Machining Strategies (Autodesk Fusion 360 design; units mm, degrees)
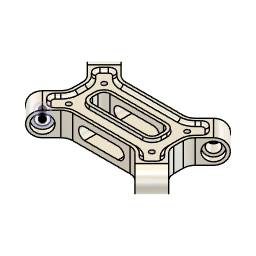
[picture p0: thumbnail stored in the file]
base_feature "Base Feature1" bodies "Screw", "Pull Stud", "Base", "Pull Stud (1)", "Pull Stud (2)", "Pull Stud (3)"
base_feature "Base Feature1"
base_feature "Base Feature1"
as_built_joint "As-built1"
as_built_joint "As-built4"
as_built_joint "As-built2" OffsetX 0 OffsetY 0 OffsetZ 0 AngleZ 0 DistanceMinimum 0
as_built_joint "As-built3" OffsetX 0 OffsetY 0 OffsetZ 0 AngleZ 0 DistanceMinimum 0
motion_link "MotionLink1" Value1 10 Value2 10
sketch "Stock Top Profile" plane through (0, 0, 0) normal (0, 1, 0) x axis (1, 0, 0)
  line L1 (-76.2, -12.7) -> (76.2, -12.7)
  line L2 (-76.2, 12.7) -> (-76.2, -12.7)
  line L3 (76.2, 12.7) -> (-76.2, 12.7)
  line L4 (76.2, -12.7) -> (76.2, 12.7)
  line L5 (-76.2, 12.7) -> (76.2, -12.7)
  line L6 (76.2, 12.7) -> (-76.2, -12.7)
  point P6 (0, 0)
  point P1 (0, 0)
  point P4 (-76.2, 12.7)
  point P5 (76.2, 12.7)
  point P3 (-76.2, -12.7)
  perpendicular L1 L2
  parallel L1 L3
  parallel L2 L4
  horizontal L1
  coincident L5 P6
  coincident L6 P6
  coincident P1 P6
  dimension "d13" distance P4 P5 = 152.4
  dimension "d14" distance P3 P4 = 25.4
  dimension "d21" OffsetX = 0
  dimension "d22" OffsetY = 0
  dimension "d23" OffsetZ = 0
  dimension "d24" AngleZ = 0
  dimension "d172" OffsetX = 0
  dimension "d173" OffsetY = 0
  dimension "d174" OffsetZ = 0
  dimension "d175" AngleZ = 0
  dimension "d188" OffsetX = 0
  dimension "d189" OffsetY = 0
  dimension "d190" OffsetZ = 0
  dimension "d191" AngleZ = 0
  dimension "d218" OffsetX = 0
  dimension "d219" OffsetY = 0
  dimension "d220" OffsetZ = 0
  dimension "d221" AngleZ = 0
  dimension "d238" OffsetX = 0
  dimension "d239" OffsetY = 0
  dimension "d240" OffsetZ = 0
  dimension "d241" AngleZ = 0
  dimension "d270" OffsetX = 0
  dimension "d271" OffsetY = 0
  dimension "d272" OffsetZ = 0
  dimension "d273" AngleZ = 0
extrude "Extrude1" new body sketch "Stock Top Profile" profile of L1 L2 L3 L4 along normal blind 38.1
sketch "Sketch1" plane through (0, 0, 25.6902) normal (0, 0, 1) x axis (1, 0, 0)
  line L1 (-62.3, 41.746) -> (-62.3, 43.3968)
  line L2 (62.3, 41.746) -> (-62.3, 41.746)
  line L3 (62.3, 43.3968) -> (62.3, 41.746)
  line L4 (-62.3, 43.3968) -> (62.3, 43.3968)
  line L5 (0, 40.3968) -> (0, 43.3968)
  line L6 (-62.3, 40.3968) -> (62.3, 40.3968)
  point P6 (0, 43.3968)
  point P7 (0, 40.3968)
  midpoint L4 P6
  perpendicular L2 L5
  coincident P7 L6
joint_origin "JointOrigin1" OffsetX 0 OffsetY 0 OffsetZ 0 AngleZ 0
joint "Assemble1" alignAngle 0 alignOffsetX 0 alignOffsetY 0 alignOffsetZ 0
joint "Assemble3" alignAngle 0 alignOffsetX 0 alignOffsetY 0 alignOffsetZ 0
sketch "Step Profile" plane through (76.2, 0, 0) normal (1, 0, 0) x axis (0, 0, -1)
  line L1 (12.7, 0) -> (-12.7, 0)
  line L2 (12.7, 38.1) -> (12.7, 0)
  line L3 (-12.7, 38.1) -> (12.7, 38.1)
  line L4 (-12.7, 0) -> (-12.7, 38.1)
  line L5 (-50.8, 38.1) -> (50.8, 38.1)
  line L6 (-50.8, 6.731) -> (-50.8, 38.1)
  line L7 (50.8, 6.731) -> (-50.8, 6.731)
  line L8 (50.8, 38.1) -> (50.8, 6.731)
  line L9 (-50.8, 6.731) -> (50.8, 38.1)
  line L10 (50.8, 6.731) -> (-50.8, 38.1)
  point P10 (0, 22.4155)
  point P1 (0, 0)
  point P6 (50.8, 38.1)
  point P7 (-50.8, 38.1)
  perpendicular L5 L6
  parallel L5 L7
  parallel L6 L8
  horizontal L5
  coincident L9 P10
  coincident L10 P10
  vertical P1 P10
  collinear L3 L5
  dimension "d184" distance P6 P7 = 101.6
  dimension "d185" distance L1 L7 = 6.731
extrude "Extrude2" add sketch "Step Profile" profile of L2 L4 L5 L6 L7 L8 to an object
copy_paste "CutPaste1"
copy_paste "CutPaste2"
copy_paste "CutPaste3"
copy_paste "CutPaste4"
as_built_joint "As-built5"
base_feature "Base Feature1"
joint "Assemble4" alignAngle 0 alignOffsetX 0 alignOffsetY 0 alignOffsetZ 0
copy_paste "CutPaste5"
base_feature "Base Feature1"
base_feature "Base Feature1" bodies "Pull Stud (1)", "Pull Stud (2)", "Base", "Screw", "Pull Stud (3)", "Pull Stud"
base_feature "Base Feature1"
base_feature "Base Feature1" bodies "Body1"
sketch "Sketch1" plane through (0, 85.85, 0) normal (0, 1, 0) x axis (-1, 0, 0)
  line L1 (62.3776, 12.3492) -> (-62.2224, 12.3492)
  line L2 (62.3776, 14) -> (62.3776, 12.3492)
  line L3 (-62.2224, 14) -> (62.3776, 14)
  line L4 (-62.2224, 12.3492) -> (-62.2224, 14)
  line L5 (62.3776, 11) -> (-62.2224, 11)
  line L6 (62.3776, 3) -> (-62.2224, 3)
joint_origin "JointOrigin1" OffsetX 0 named "d5_1" OffsetY 0 named "d6_1" OffsetZ 0 named "d7_1" AngleZ 0 named "d8_1"
joint_origin "JointOrigin2" OffsetX 0 named "d9_1" OffsetY 0 named "d10_1" OffsetZ 0 named "d11_1" AngleZ 0 named "d12_1"
copy_paste "CopyPaste1"
as_built_joint "As-built1"
as_built_joint "As-built2"
as_built_joint "As-built3" OffsetX 0 named "d13_1" OffsetY 0 named "d14_1" OffsetZ 0 named "d15_1" AngleZ 0 named "d16_1"
as_built_joint "As-built4" OffsetX 0 named "d17_1" OffsetY 0 named "d18_1" OffsetZ 0 named "d19_1" AngleZ 0 named "d20_1"
motion_link "MotionLink1" Value1 10 named "d21_1" Value2 10 named "d22_1"
sketch "Sketch1" plane through (0, 0, 0) normal (0, 1, 0) x axis (1, 0, 0)
  line L1 (-95.25, -50.8) -> (95.25, -50.8)
  line L2 (-95.25, 50.8) -> (-95.25, -50.8)
  line L3 (95.25, 50.8) -> (-95.25, 50.8)
  line L4 (95.25, -50.8) -> (95.25, 50.8)
  line L5 (-95.25, 50.8) -> (95.25, -50.8)
  line L6 (95.25, 50.8) -> (-95.25, -50.8)
  point P6 (0, 0)
  point P1 (0, 0)
  point P4 (-95.25, 50.8)
  point P5 (95.25, 50.8)
  point P3 (-95.25, -50.8)
  perpendicular L1 L2
  parallel L1 L3
  parallel L2 L4
  horizontal L1
  coincident L5 P6
  coincident L6 P6
  coincident P1 P6
  dimension "d23_1" distance P4 P5 = 190.5
  dimension "d24_1" distance P3 P4 = 101.6
extrude "Extrude1" new body sketch "Sketch1" profile of L1 L2 L3 L4 along normal blind 50.8 named "d25_1"
position "Position2"
joint "Assemble1" alignAngle 180 alignOffsetX 0 alignOffsetY 0 alignOffsetZ 0
joint "Assemble2" alignAngle 0 alignOffsetX 0 alignOffsetY 0 named "d41_1" alignOffsetZ 0 named "d42_1"
joint "Assemble10" OffsetX 0 OffsetY 0 OffsetZ 0 AngleZ 0 alignAngle 0 alignOffsetX 0 alignOffsetY 0 alignOffsetZ 0
sketch "Stock Top Profile" plane through (0, 0, 0) normal (0, 1, 0) x axis (1, 0, 0)
  line L1 (-76.2, -12.7) -> (76.2, -12.7)
  line L2 (-76.2, 12.7) -> (-76.2, -12.7)
  line L3 (76.2, 12.7) -> (-76.2, 12.7)
  line L4 (76.2, -12.7) -> (76.2, 12.7)
  line L5 (-76.2, 12.7) -> (76.2, -12.7)
  line L6 (76.2, 12.7) -> (-76.2, -12.7)
  point P6 (0, 0)
  point P1 (0, 0)
  point P4 (-76.2, 12.7)
  point P5 (76.2, 12.7)
  point P3 (-76.2, -12.7)
  perpendicular L1 L2
  parallel L1 L3
  parallel L2 L4
  horizontal L1
  coincident L5 P6
  coincident L6 P6
  coincident P1 P6
  dimension "d13_2" distance P4 P5 = 152.4
  dimension "d14_2" distance P3 P4 = 25.4
  dimension "d21_2" OffsetX = 0
  dimension "d22_2" OffsetY = 0
  dimension "d23_2" OffsetZ = 0
  dimension "d24_2" AngleZ = 0
  dimension "d172_1" OffsetX = 0
  dimension "d173_1" OffsetY = 0
  dimension "d174_1" OffsetZ = 0
  dimension "d175_1" AngleZ = 0
  dimension "d188_1" OffsetX = 0
  dimension "d189_1" OffsetY = 0
  dimension "d190_1" OffsetZ = 0
  dimension "d191_1" AngleZ = 0
  dimension "d218_1" OffsetX = 0
  dimension "d219_1" OffsetY = 0
  dimension "d220_1" OffsetZ = 0
  dimension "d221_1" AngleZ = 0
  dimension "d238_1" OffsetX = 0
  dimension "d239_1" OffsetY = 0
  dimension "d240_1" OffsetZ = 0
  dimension "d241_1" AngleZ = 0
  dimension "d270_1" OffsetX = 0
  dimension "d271_1" OffsetY = 0
  dimension "d272_1" OffsetZ = 0
  dimension "d273_1" AngleZ = 0
extrude "Extrude1" new body sketch "Stock Top Profile" profile of L1 L2 L3 L4 along normal blind 38.1 named "d15_2"
position "Position4"
position "Position5"
joint_origin "JointOrigin3" OffsetX 0 named "d41_2" OffsetY 0 named "d42_2" OffsetZ 0 named "d43_1" AngleZ 0 named "d44_1"
joint_origin "JointOrigin4" OffsetX 0 named "d49_1" OffsetY 0 named "d50_1" OffsetZ 0 named "d51_1" AngleZ 0 named "d52_1"
sketch "Step Profile" plane through (76.2, 0, 0) normal (1, 0, 0) x axis (0, 0, -1)
  line L1 (12.7, 0) -> (-12.7, 0)
  line L2 (12.7, 38.1) -> (12.7, 0)
  line L3 (-12.7, 38.1) -> (12.7, 38.1)
  line L4 (-12.7, 0) -> (-12.7, 38.1)
  line L5 (-50.8, 38.1) -> (50.8, 38.1)
  line L6 (-50.8, 6.731) -> (-50.8, 38.1)
  line L7 (50.8, 6.731) -> (-50.8, 6.731)
  line L8 (50.8, 38.1) -> (50.8, 6.731)
  line L9 (-50.8, 6.731) -> (50.8, 38.1)
  line L10 (50.8, 6.731) -> (-50.8, 38.1)
  point P10 (0, 22.4155)
  point P1 (0, 0)
  point P6 (50.8, 38.1)
  point P7 (-50.8, 38.1)
  perpendicular L5 L6
  parallel L5 L7
  parallel L6 L8
  horizontal L5
  coincident L9 P10
  coincident L10 P10
  vertical P1 P10
  collinear L3 L5
  dimension "d184_1" distance P6 P7 = 101.6
  dimension "d185_1" distance L1 L7 = 6.731
extrude "Extrude2" add sketch "Step Profile" profile of L2 L4 L5 L6 L7 L8 to an object
joint_origin "JointOrigin13" OffsetX 0 named "d262_1" OffsetY 0 named "d263_1" OffsetZ 0 named "d264_1" AngleZ 0 named "d265_1"
as_built_joint "As-built6"
sketch "Sketch3" plane through (0, 38.1, 0) normal (0, 1, 0) x axis (-1, 0, 0)
  line L1 (76.2, 50.8) -> (76.2, -50.8)
  line L2 (-76.2, 50.8) -> (76.2, 50.8)
  line L3 (-76.2, -50.8) -> (-76.2, 50.8)
  line L4 (76.2, -50.8) -> (-76.2, -50.8)
  line L5 (-76.2, -32.8395) -> (-58.2395, -50.8)
  line L6 (-53.7494, -10.3888) -> (-76.2, -32.8395)
  line L7 (-35.7888, -28.3494) -> (-58.2395, -50.8)
  line L8 (-25.2088, 0) -> (0, 0)
  line L9 (-53.7494, 0) -> (-53.7494, -10.3888)
  line L10 (9.7506, -28.3494) -> (-35.7888, -28.3494)
  line L11 (25.4, -12.7) -> (9.7506, -28.3494)
  line L12 (76.2, -12.7) -> (25.4, -12.7)
  line L13 (76.2, 0) -> (76.2, -12.7)
  line L14 (76.2, 0) -> (76.2, 12.7)
  line L15 (76.2, 12.7) -> (25.4, 12.7)
  line L16 (25.4, 12.7) -> (9.7506, 28.3494)
  line L17 (9.7506, 28.3494) -> (-35.7888, 28.3494)
  line L18 (-35.7888, 28.3494) -> (-58.2395, 50.8)
  line L19 (-76.2, 32.8395) -> (-58.2395, 50.8)
  line L20 (-53.7494, 10.3888) -> (-76.2, 32.8395)
  line L21 (-53.7494, 0) -> (-53.7494, 10.3888)
  line L22 (0, -18.5532) -> (0, 0)
  line L23 (35.7888, -28.3494) -> (58.2395, -50.8)
  line L24 (76.2, -32.8395) -> (58.2395, -50.8)
  line L25 (53.7494, -10.3888) -> (76.2, -32.8395)
  line L26 (53.7494, 0) -> (53.7494, -10.3888)
  line L27 (53.7494, 0) -> (53.7494, 10.3888)
  line L28 (53.7494, 10.3888) -> (76.2, 32.8395)
  line L29 (76.2, 32.8395) -> (58.2395, 50.8)
  line L30 (35.7888, 28.3494) -> (58.2395, 50.8)
  line L31 (9.7506, -28.3494) -> (35.7888, -28.3494)
  line L32 (9.7506, 28.3494) -> (35.7888, 28.3494)
  point P6 (-58.2395, -50.8)
  point P7 (-76.2, -32.8395)
  point P1 (0, 0)
  point P10 (0, 0)
  point P11 (-25.2088, 0)
  point P12 (-53.7494, 0)
  point P15 (76.2, -12.7)
  point P16 (76.2, 0)
  point P22 (-58.2395, 50.8)
  point P23 (-76.2, 32.8395)
  point P8 (-53.7494, -10.3888)
  point P24 (-53.7494, 10.3888)
  point P9 (-35.7888, -28.3494)
  point P21 (-35.7888, 28.3494)
  point P25 (-53.7494, 0)
  point P13 (9.7506, -28.3494)
  point P20 (9.7506, 28.3494)
  point P14 (25.4, -12.7)
  point P19 (25.4, 12.7)
  point P17 (76.2, 12.7)
  point P18 (76.2, 0)
  point P26 (0, 0)
  point P28 (58.2395, -50.8)
  point P30 (76.2, -32.8395)
  point P31 (53.7494, -10.3888)
  point P29 (35.7888, -28.3494)
  point P32 (53.7494, 0)
  point P37 (35.7888, 28.3494)
  point P36 (58.2395, 50.8)
  point P35 (76.2, 32.8395)
  point P33 (53.7494, 10.3888)
  point P34 (53.7494, 0)
  coincident L4 P6
  coincident L3 P7
  perpendicular L5 L6
  perpendicular L5 L7
  coincident P1 P10
  horizontal L8
  equal L6 L7
  perpendicular L8 L9
  horizontal P11 P12
  horizontal L10
  parallel L7 L11
  coincident L1 P15
  perpendicular L1 L12
  midpoint L1 P16
  symmetric P6 L8 P22
  symmetric P7 L8 P23
  symmetric P8 L8 P24
  symmetric P9 L8 P21
  symmetric L8 P12 P25
  symmetric L8 P13 P20
  symmetric L8 P14 P19
  symmetric L8 P15 P17
  symmetric L8 P16 P18
  coincident P1 P26
  perpendicular L8 L22
  symmetric P6 L22 P28
  symmetric P7 L22 P30
  symmetric P8 L22 P31
  symmetric P9 L22 P29
  symmetric P12 L22 P32
  symmetric P21 L22 P37
  symmetric P22 L22 P36
  symmetric P23 L22 P35
  symmetric P24 L22 P33
  symmetric P25 L22 P34
  dimension "d335" angle L4 L5 = 45
  dimension "d336" distance P6 P7 = 25.4
  dimension "d337" distance P7 P8 = 31.75
  dimension "d338" distance P15 P16 = 12.7
  dimension "d339" distance P14 P15 = 50.8
extrude "Extrude3" cut sketch "Sketch3" profile of L1 L2 L3 L4 L5 L6 L7 L9 L10 L12 L13 L14 L15 L17 L18 L19 L20 L21 L23 L24 L25 L26 L27 L28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 no distance stored
split "Split1"
remove_body "RemoveBody1"
offset_faces "OffsetFaces1" distance -5.969
fillet "Fillet1" radius 12.7
fillet "Fillet2" radius 12.7
sketch "Sketch5" plane through (3.7197, 0, -3.7197) normal (-0.7071, 0, 0.7071) x axis (0.7071, 0, 0.7071)
  line L1 (64.4026, 12.7) -> (50.6131, 12.7)
  line L2 (50.6131, 38.1) -> (64.4026, 38.1)
  line L3 (53.7881, 15.875) -> (53.7881, 34.925)
  line L4 (64.4026, 15.875) -> (53.7881, 15.875)
  line L5 (53.7881, 34.925) -> (64.4026, 34.925)
  line L6 (50.6131, 12.7) -> (50.6131, 38.1)
  arc A1 centre (64.4026, 25.4) radius 12.7 clockwise from (64.4026, 38.1) to (64.4026, 12.7)
  circle C1 centre (64.4026, 25.4) radius 6.35
  arc A2 centre (64.4026, 25.4) radius 9.525 clockwise from (64.4026, 34.925) to (64.4026, 15.875)
  arc A3 centre (64.4026, 25.4) radius 9.525 clockwise from (64.4026, 15.875) to (64.4026, 34.925)
  concentric A1 C1
  tangent L4 A3
  parallel L1 L4
  concentric A1 A2
  parallel L2 L5
  tangent A2 L5
  tangent L4 A2
  dimension "d346" diameter C1 = 12.7
extrude "Extrude4" cut sketch "Sketch5" profile of C1 no distance stored
extrude "Extrude5" cut sketch "Sketch5" profile of C1 A2 A3 against normal blind 6.35
work_plane "WorkPlane1"
mirror "Mirror1"
mirror "Mirror2"
mirror "Mirror3"
sketch "Sketch10" plane through (0, 38.1, 0) normal (0, 1, 0) x axis (-1, 0, 0)
  line L1 (67.2197, -23.8592) -> (49.2592, -41.8197)
  line L2 (57.4691, -14.1086) -> (67.2197, -23.8592)
  line L3 (53.7494, 5.1283) -> (53.7494, -5.1283)
  line L4 (67.2197, 23.8592) -> (57.4691, 14.1086)
  line L5 (49.2592, 41.8197) -> (67.2197, 23.8592)
  line L6 (39.5086, 32.0691) -> (49.2592, 41.8197)
  line L7 (-30.5283, 28.3494) -> (30.5283, 28.3494)
  line L8 (-49.2592, 41.8197) -> (-39.5086, 32.0691)
  line L9 (-67.2197, 23.8592) -> (-49.2592, 41.8197)
  line L10 (-57.4691, 14.1086) -> (-67.2197, 23.8592)
  line L11 (-53.7494, -5.1283) -> (-53.7494, 5.1283)
  line L12 (-67.2197, -23.8592) -> (-57.4691, -14.1086)
  line L13 (-49.2592, -41.8197) -> (-67.2197, -23.8592)
  line L14 (-39.5086, -32.0691) -> (-49.2592, -41.8197)
  line L15 (30.5283, -28.3494) -> (-30.5283, -28.3494)
  line L16 (49.2592, -41.8197) -> (39.5086, -32.0691)
  line L17 (34.925, -9.2994) -> (-34.925, -9.2994)
  line L18 (34.925, 9.2994) -> (34.925, -9.2994)
  line L19 (-34.925, 9.2994) -> (34.925, 9.2994)
  line L20 (-34.925, -9.2994) -> (-34.925, 9.2994)
  line L21 (34.925, 9.2994) -> (-34.925, -9.2994)
  line L22 (-34.925, 9.2994) -> (34.925, -9.2994)
  arc A1 centre (66.4494, -5.1283) radius 12.7 clockwise from (57.4691, -14.1086) to (53.7494, -5.1283)
  arc A2 centre (66.4494, 5.1283) radius 12.7 clockwise from (53.7494, 5.1283) to (57.4691, 14.1086)
  arc A3 centre (30.5283, 41.0494) radius 12.7 clockwise from (39.5086, 32.0691) to (30.5283, 28.3494)
  arc A4 centre (-30.5283, 41.0494) radius 12.7 clockwise from (-30.5283, 28.3494) to (-39.5086, 32.0691)
  arc A5 centre (-66.4494, 5.1283) radius 12.7 clockwise from (-57.4691, 14.1086) to (-53.7494, 5.1283)
  arc A6 centre (-66.4494, -5.1283) radius 12.7 clockwise from (-53.7494, -5.1283) to (-57.4691, -14.1086)
  arc A7 centre (-30.5283, -41.0494) radius 12.7 clockwise from (-39.5086, -32.0691) to (-30.5283, -28.3494)
  arc A8 centre (30.5283, -41.0494) radius 12.7 clockwise from (30.5283, -28.3494) to (39.5086, -32.0691)
  point P38 (0, 0)
  point P1 (0, 0)
  point P34 (-34.925, -9.2994)
  point P35 (34.925, -9.2994)
  perpendicular L17 L18
  parallel L17 L19
  parallel L18 L20
  horizontal L17
  coincident L21 P38
  coincident L22 P38
  coincident P1 P38
  dimension "d373" distance L15 L17 = 19.05
  dimension "d374" distance P34 P35 = 69.85
extrude "Extrude11" cut sketch "Sketch10" profile of L17 L18 L19 L20 no distance stored
fillet "Fillet6" radius 6.35
sketch "Sketch11" plane through (0, 38.1, 0) normal (0, 1, 0) x axis (-1, 0, 0)
  line L1 (28.575, 9.2994) -> (-28.575, 9.2994)
  line L2 (34.925, -2.9494) -> (34.925, 2.9494)
  line L3 (-28.575, -9.2994) -> (28.575, -9.2994)
  line L4 (-34.925, 2.9494) -> (-34.925, -2.9494)
  line L5 (67.2197, -23.8592) -> (49.2592, -41.8197)
  line L6 (57.4691, -14.1086) -> (67.2197, -23.8592)
  line L7 (53.7494, 5.1283) -> (53.7494, -5.1283)
  line L8 (67.2197, 23.8592) -> (57.4691, 14.1086)
  line L9 (49.2592, 41.8197) -> (67.2197, 23.8592)
  line L10 (39.5086, 32.0691) -> (49.2592, 41.8197)
  line L11 (-30.5283, 28.3494) -> (30.5283, 28.3494)
  line L12 (-49.2592, 41.8197) -> (-39.5086, 32.0691)
  line L13 (-67.2197, 23.8592) -> (-49.2592, 41.8197)
  line L14 (-57.4691, 14.1086) -> (-67.2197, 23.8592)
  line L15 (-53.7494, -5.1283) -> (-53.7494, 5.1283)
  line L16 (-67.2197, -23.8592) -> (-57.4691, -14.1086)
  line L17 (-49.2592, -41.8197) -> (-67.2197, -23.8592)
  line L18 (-39.5086, -32.0691) -> (-49.2592, -41.8197)
  line L19 (30.5283, -28.3494) -> (-30.5283, -28.3494)
  line L20 (49.2592, -41.8197) -> (39.5086, -32.0691)
  line L21 (30.5283, -25.1744) -> (-30.5283, -25.1744)
  line L22 (49.2592, -37.3296) -> (41.7537, -29.824)
  line L23 (62.7296, -23.8592) -> (49.2592, -37.3296)
  line L24 (55.224, -16.3537) -> (62.7296, -23.8592)
  line L25 (50.5744, 5.1283) -> (50.5744, -5.1283)
  line L26 (62.7296, 23.8592) -> (55.224, 16.3537)
  line L27 (49.2592, 37.3296) -> (62.7296, 23.8592)
  line L28 (41.7537, 29.824) -> (49.2592, 37.3296)
  line L29 (-30.5283, 25.1744) -> (30.5283, 25.1744)
  line L30 (-49.2592, 37.3296) -> (-41.7537, 29.824)
  line L31 (-62.7296, 23.8592) -> (-49.2592, 37.3296)
  line L32 (-55.224, 16.3537) -> (-62.7296, 23.8592)
  line L33 (-50.5744, -5.1283) -> (-50.5744, 5.1283)
  line L34 (-62.7296, -23.8592) -> (-55.224, -16.3537)
  line L35 (-49.2592, -37.3296) -> (-62.7296, -23.8592)
  line L36 (-41.7537, -29.824) -> (-49.2592, -37.3296)
  line L37 (-28.575, -12.4744) -> (28.575, -12.4744)
  line L38 (38.1, -2.9494) -> (38.1, 2.9494)
  line L39 (28.575, 12.4744) -> (-28.575, 12.4744)
  line L40 (-38.1, 2.9494) -> (-38.1, -2.9494)
  arc A1 centre (28.575, 2.9494) radius 6.35 clockwise from (28.575, 9.2994) to (34.925, 2.9494)
  arc A2 centre (28.575, -2.9494) radius 6.35 clockwise from (34.925, -2.9494) to (28.575, -9.2994)
  arc A3 centre (-28.575, -2.9494) radius 6.35 clockwise from (-28.575, -9.2994) to (-34.925, -2.9494)
  arc A4 centre (-28.575, 2.9494) radius 6.35 clockwise from (-34.925, 2.9494) to (-28.575, 9.2994)
  arc A5 centre (66.4494, -5.1283) radius 12.7 clockwise from (57.4691, -14.1086) to (53.7494, -5.1283)
  arc A6 centre (66.4494, 5.1283) radius 12.7 clockwise from (53.7494, 5.1283) to (57.4691, 14.1086)
  arc A7 centre (30.5283, 41.0494) radius 12.7 clockwise from (39.5086, 32.0691) to (30.5283, 28.3494)
  arc A8 centre (-30.5283, 41.0494) radius 12.7 clockwise from (-30.5283, 28.3494) to (-39.5086, 32.0691)
  arc A9 centre (-66.4494, 5.1283) radius 12.7 clockwise from (-57.4691, 14.1086) to (-53.7494, 5.1283)
  arc A10 centre (-66.4494, -5.1283) radius 12.7 clockwise from (-53.7494, -5.1283) to (-57.4691, -14.1086)
  arc A11 centre (-30.5283, -41.0494) radius 12.7 clockwise from (-39.5086, -32.0691) to (-30.5283, -28.3494)
  arc A12 centre (30.5283, -41.0494) radius 12.7 clockwise from (30.5283, -28.3494) to (39.5086, -32.0691)
  arc A13 centre (30.5283, -41.0494) radius 15.875 clockwise from (30.5283, -25.1744) to (41.7537, -29.824)
  arc A14 centre (66.4494, -5.1283) radius 15.875 clockwise from (55.224, -16.3537) to (50.5744, -5.1283)
  arc A15 centre (66.4494, 5.1283) radius 15.875 clockwise from (50.5744, 5.1283) to (55.224, 16.3537)
  arc A16 centre (30.5283, 41.0494) radius 15.875 clockwise from (41.7537, 29.824) to (30.5283, 25.1744)
  arc A17 centre (-30.5283, 41.0494) radius 15.875 clockwise from (-30.5283, 25.1744) to (-41.7537, 29.824)
  arc A18 centre (-66.4494, 5.1283) radius 15.875 clockwise from (-55.224, 16.3537) to (-50.5744, 5.1283)
  arc A19 centre (-66.4494, -5.1283) radius 15.875 clockwise from (-50.5744, -5.1283) to (-55.224, -16.3537)
  arc A20 centre (-30.5283, -41.0494) radius 15.875 clockwise from (-41.7537, -29.824) to (-30.5283, -25.1744)
  arc A21 centre (-28.575, -2.9494) radius 9.525 clockwise from (-28.575, -12.4744) to (-38.1, -2.9494)
  arc A22 centre (28.575, -2.9494) radius 9.525 clockwise from (38.1, -2.9494) to (28.575, -12.4744)
  arc A23 centre (28.575, 2.9494) radius 9.525 clockwise from (28.575, 12.4744) to (38.1, 2.9494)
  arc A24 centre (-28.575, 2.9494) radius 9.525 clockwise from (-38.1, 2.9494) to (-28.575, 12.4744)
  dimension "d377" = 3.175
  dimension "d378" = -3.175
extrude "Extrude12" cut sketch "Sketch11" profile of L28 A15 L21 L22 L25 A13 L23 L24 L32 L26 A14 L27 A16 L29 A17 L30 L31 A18 L33 A19 L34 L35 L36 A20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 against normal blind 3.175
fillet "Fillet7" radius 6.35
work_plane "WorkPlane2"
mirror "Mirror4"
sketch "Sketch12" plane through (0, 0, 28.3494) normal (0, 0, 1) x axis (1, 0, 0)
  line L1 (-30.5283, 12.7) -> (-30.5283, 38.1)
  line L2 (30.5283, 12.7) -> (-30.5283, 12.7)
  line L3 (30.5283, 38.1) -> (30.5283, 12.7)
  line L4 (-30.5283, 38.1) -> (30.5283, 38.1)
  line L5 (24.1783, 19.05) -> (-24.1783, 19.05)
  line L6 (24.1783, 31.75) -> (24.1783, 19.05)
  line L7 (-24.1783, 31.75) -> (24.1783, 31.75)
  line L8 (-24.1783, 19.05) -> (-24.1783, 31.75)
  dimension "d383" = -6.35
extrude "Extrude13" cut sketch "Sketch12" profile of L8 L5 L6 L7 no distance stored
fillet "Fillet8" radius 6.35
sketch "Sketch13" plane through (0, 34.925, 0) normal (0, 1, 0) x axis (-1, 0, 0)
  line L1 (-28.575, -12.4744) -> (28.575, -12.4744)
  line L2 (-38.1, 2.9494) -> (-38.1, -2.9494)
  line L3 (28.575, 12.4744) -> (-28.575, 12.4744)
  line L4 (38.1, -2.9494) -> (38.1, 2.9494)
  line L5 (-58.2395, 28.3494) -> (-53.7494, 32.8395)
  line L6 (-55.224, 16.3537) -> (-58.2395, 19.3691)
  line L7 (-50.5744, -5.1283) -> (-50.5744, 5.1283)
  line L8 (-58.2395, -19.3691) -> (-55.224, -16.3537)
  line L9 (-53.7494, -32.8395) -> (-58.2395, -28.3494)
  line L10 (-41.7537, -29.824) -> (-44.7691, -32.8395)
  line L11 (30.5283, -25.1744) -> (-30.5283, -25.1744)
  line L12 (44.7691, -32.8395) -> (41.7537, -29.824)
  line L13 (58.2395, -28.3494) -> (53.7494, -32.8395)
  line L14 (55.224, -16.3537) -> (58.2395, -19.3691)
  line L15 (50.5744, 5.1283) -> (50.5744, -5.1283)
  line L16 (58.2395, 19.3691) -> (55.224, 16.3537)
  line L17 (53.7494, 32.8395) -> (58.2395, 28.3494)
  line L18 (41.7537, 29.824) -> (44.7691, 32.8395)
  line L19 (-30.5283, 25.1744) -> (30.5283, 25.1744)
  line L20 (-44.7691, 32.8395) -> (-41.7537, 29.824)
  line L21 (36.6034, -26.3828) -> (51.7828, -11.2034)
  arc A1 centre (28.575, -2.9494) radius 9.525 clockwise from (38.1, -2.9494) to (28.575, -12.4744)
  arc A2 centre (-28.575, -2.9494) radius 9.525 clockwise from (-28.575, -12.4744) to (-38.1, -2.9494)
  arc A3 centre (-28.575, 2.9494) radius 9.525 clockwise from (-38.1, 2.9494) to (-28.575, 12.4744)
  arc A4 centre (28.575, 2.9494) radius 9.525 clockwise from (28.575, 12.4744) to (38.1, 2.9494)
  arc A5 centre (-49.2592, 28.3494) radius 6.35 clockwise from (-53.7494, 32.8395) to (-44.7691, 32.8395)
  arc A6 centre (-53.7494, 23.8592) radius 6.35 clockwise from (-58.2395, 19.3691) to (-58.2395, 28.3494)
  arc A7 centre (-66.4494, 5.1283) radius 15.875 clockwise from (-55.224, 16.3537) to (-50.5744, 5.1283)
  arc A8 centre (-66.4494, -5.1283) radius 15.875 clockwise from (-50.5744, -5.1283) to (-55.224, -16.3537)
  arc A9 centre (-53.7494, -23.8592) radius 6.35 clockwise from (-58.2395, -28.3494) to (-58.2395, -19.3691)
  arc A10 centre (-49.2592, -28.3494) radius 6.35 clockwise from (-44.7691, -32.8395) to (-53.7494, -32.8395)
  arc A11 centre (-30.5283, -41.0494) radius 15.875 clockwise from (-41.7537, -29.824) to (-30.5283, -25.1744)
  arc A12 centre (30.5283, -41.0494) radius 15.875 clockwise from (30.5283, -25.1744) to (41.7537, -29.824)
  arc A13 centre (49.2592, -28.3494) radius 6.35 clockwise from (53.7494, -32.8395) to (44.7691, -32.8395)
  arc A14 centre (53.7494, -23.8592) radius 6.35 clockwise from (58.2395, -19.3691) to (58.2395, -28.3494)
  arc A15 centre (66.4494, -5.1283) radius 15.875 clockwise from (55.224, -16.3537) to (50.5744, -5.1283)
  arc A16 centre (66.4494, 5.1283) radius 15.875 clockwise from (50.5744, 5.1283) to (55.224, 16.3537)
  arc A17 centre (53.7494, 23.8592) radius 6.35 clockwise from (58.2395, 28.3494) to (58.2395, 19.3691)
  arc A18 centre (49.2592, 28.3494) radius 6.35 clockwise from (44.7691, 32.8395) to (53.7494, 32.8395)
  arc A19 centre (30.5283, 41.0494) radius 15.875 clockwise from (41.7537, 29.824) to (30.5283, 25.1744)
  arc A20 centre (-30.5283, 41.0494) radius 15.875 clockwise from (-30.5283, 25.1744) to (-41.7537, 29.824)
  circle C1 centre (44.1931, -18.7931) radius 2.5527
  point P63 (51.7828, -11.2034)
  point P64 (36.6034, -26.3828)
  point P62 (44.1931, -18.7931)
  midpoint A15 P63
  midpoint A12 P64
  midpoint P62 L21
  dimension "d386" diameter C1 = 5.1054
extrude "Extrude14" cut sketch "Sketch13" profile of C1 no distance stored
mirror "Mirror5"
mirror "Mirror6"
sketch "2D contour Outside" plane through (0, 38.1, 0) normal (0, 1, 0) x axis (-1, 0, 0)
  line L1 (57.4691, -14.1086) -> (67.2197, -23.8592)
  line L2 (53.7494, 5.1283) -> (53.7494, -5.1283)
  line L3 (67.2197, 23.8592) -> (57.4691, 14.1086)
  line L4 (39.5086, 32.0691) -> (49.2592, 41.8197)
  line L5 (-30.5283, 28.3494) -> (30.5283, 28.3494)
  line L6 (-49.2592, 41.8197) -> (-39.5086, 32.0691)
  line L7 (-57.4691, 14.1086) -> (-67.2197, 23.8592)
  line L8 (-53.7494, -5.1283) -> (-53.7494, 5.1283)
  line L9 (-67.2197, -23.8592) -> (-57.4691, -14.1086)
  line L10 (-39.5086, -32.0691) -> (-49.2592, -41.8197)
  line L11 (30.5283, -28.3494) -> (-30.5283, -28.3494)
  line L12 (49.2592, -41.8197) -> (39.5086, -32.0691)
  line L13 (58.2395, 50.8) -> (49.2592, 41.8197)
  line L14 (67.2197, 23.8592) -> (76.2, 32.8395)
  line L15 (49.2592, -41.8197) -> (58.2395, -50.8)
  line L16 (76.2, -32.8395) -> (67.2197, -23.8592)
  line L17 (-58.2395, -50.8) -> (-49.2592, -41.8197)
  line L18 (-67.2197, -23.8592) -> (-76.2, -32.8395)
  line L19 (-76.2, 32.8395) -> (-67.2197, 23.8592)
  line L20 (-49.2592, 41.8197) -> (-58.2395, 50.8)
  line L21 (76.2, -32.8395) -> (58.2395, -50.8)
  line L22 (58.2395, 50.8) -> (76.2, 32.8395)
  line L23 (-76.2, 32.8395) -> (-58.2395, 50.8)
  line L24 (-76.2, -32.8395) -> (-58.2395, -50.8)
  arc A1 centre (66.4494, -5.1283) radius 12.7 clockwise from (57.4691, -14.1086) to (53.7494, -5.1283)
  arc A2 centre (66.4494, 5.1283) radius 12.7 clockwise from (53.7494, 5.1283) to (57.4691, 14.1086)
  arc A3 centre (30.5283, 41.0494) radius 12.7 clockwise from (39.5086, 32.0691) to (30.5283, 28.3494)
  arc A4 centre (-30.5283, 41.0494) radius 12.7 clockwise from (-30.5283, 28.3494) to (-39.5086, 32.0691)
  arc A5 centre (-66.4494, 5.1283) radius 12.7 clockwise from (-57.4691, 14.1086) to (-53.7494, 5.1283)
  arc A6 centre (-66.4494, -5.1283) radius 12.7 clockwise from (-53.7494, -5.1283) to (-57.4691, -14.1086)
  arc A7 centre (-30.5283, -41.0494) radius 12.7 clockwise from (-39.5086, -32.0691) to (-30.5283, -28.3494)
  arc A8 centre (30.5283, -41.0494) radius 12.7 clockwise from (30.5283, -28.3494) to (39.5086, -32.0691)
  point P38 (58.2395, -50.8)
  point P50 (58.2395, -50.8)
  point P41 (76.2, -32.8395)
  point P51 (76.2, -32.8395)
  point P37 (76.2, 32.8395)
  point P52 (76.2, 32.8395)
  point P35 (58.2395, 50.8)
  point P53 (58.2395, 50.8)
  point P49 (-58.2395, 50.8)
  point P54 (-58.2395, 50.8)
  point P47 (-76.2, 32.8395)
  point P55 (-76.2, 32.8395)
  point P43 (-58.2395, -50.8)
  point P56 (-58.2395, -50.8)
  point P45 (-76.2, -32.8395)
  point P57 (-76.2, -32.8395)
  coincident P38 P50
  coincident P41 P51
  coincident P37 P52
  coincident P35 P53
  coincident P49 P54
  coincident P47 P55
  coincident P43 P56
  coincident P45 P57
fillet "Fillet9" radius 3.175
sketch "Sketch1" plane through (0, 0, 0) normal (1, 0, 0) x axis (0, 1, 0)
  line L1 (120.775, 12.4739) -> (123.95, 12.4739)
  line L2 (120.775, -12.4748) -> (120.775, -21.9998)
  line L3 (120.775, 21.9989) -> (120.775, 12.4739)
  line L4 (120.775, 13.0338) -> (123.95, 12.4739)
  point P2 (123.95, 12.4739)
  point P8 (123.95, 12.4739)
  point P9 (120.775, 13.0338)
  coincident P2 P8
  coincident L3 P9
  dimension "d397" angle L1 L4 = 10
sweep "Sweep1" sketch "Sketch1" TwistAngle 0 TaperAngle 0
work_axis "WorkAxis1"
sketch "Sketch2" plane through (-8.249, 0, -8.249) normal (0.7071, 0, 0.7071) x axis (0.7071, 0, -0.7071)
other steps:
create_component "CreateComponent1"
create_component "CreateComponent2"
create_component "CreateComponent3"
joint_origin "JointOrigin3" OffsetX 0 OffsetY 0 OffsetZ 0 AngleZ 0
joint_origin "JointOrigin3" OffsetX 0 OffsetY 0 OffsetZ 0 AngleZ 0
joint_origin "JointOrigin4" OffsetX 0 OffsetY 0 OffsetZ 0 AngleZ 0
create_component "CreateComponent5"
create_component "CreateComponent7"
remove_instance "RemoveInstance1"
remove_instance "RemoveInstance2"
remove_instance "RemoveInstance3"
remove_instance "RemoveInstance4"
create_component "CreateComponent8"
joint_origin "JointOrigin1" OffsetX 0 OffsetY 0 OffsetZ 0 AngleZ 0
joint_origin "JointOrigin1" OffsetX 0 OffsetY 0 OffsetZ 0 AngleZ 0
remove_instance "RemoveInstance5"
joint_origin "JointOrigin13" OffsetX 0 OffsetY 0 OffsetZ 0 AngleZ 0
create_component "CreateComponent1"
create_component "CreateComponent2"
create_component "CreateComponent3"
create_component "CreateComponent4"
create_component "CreateComponent5"
joint_origin "JointOrigin1" OffsetX 0 named "d27_1" OffsetY 0 named "d28_1" OffsetZ 0 AngleZ 0
joint_origin "JointOrigin2" OffsetX 0 OffsetY 0 OffsetZ 0 AngleZ 0
create_component "CreateComponent10"
create_component "CreateComponent12"
named bodies: "Screw", "Pull Stud", "Base", "Pull Stud (1)", "Pull Stud (2)", "Pull Stud (3)", "Body1"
